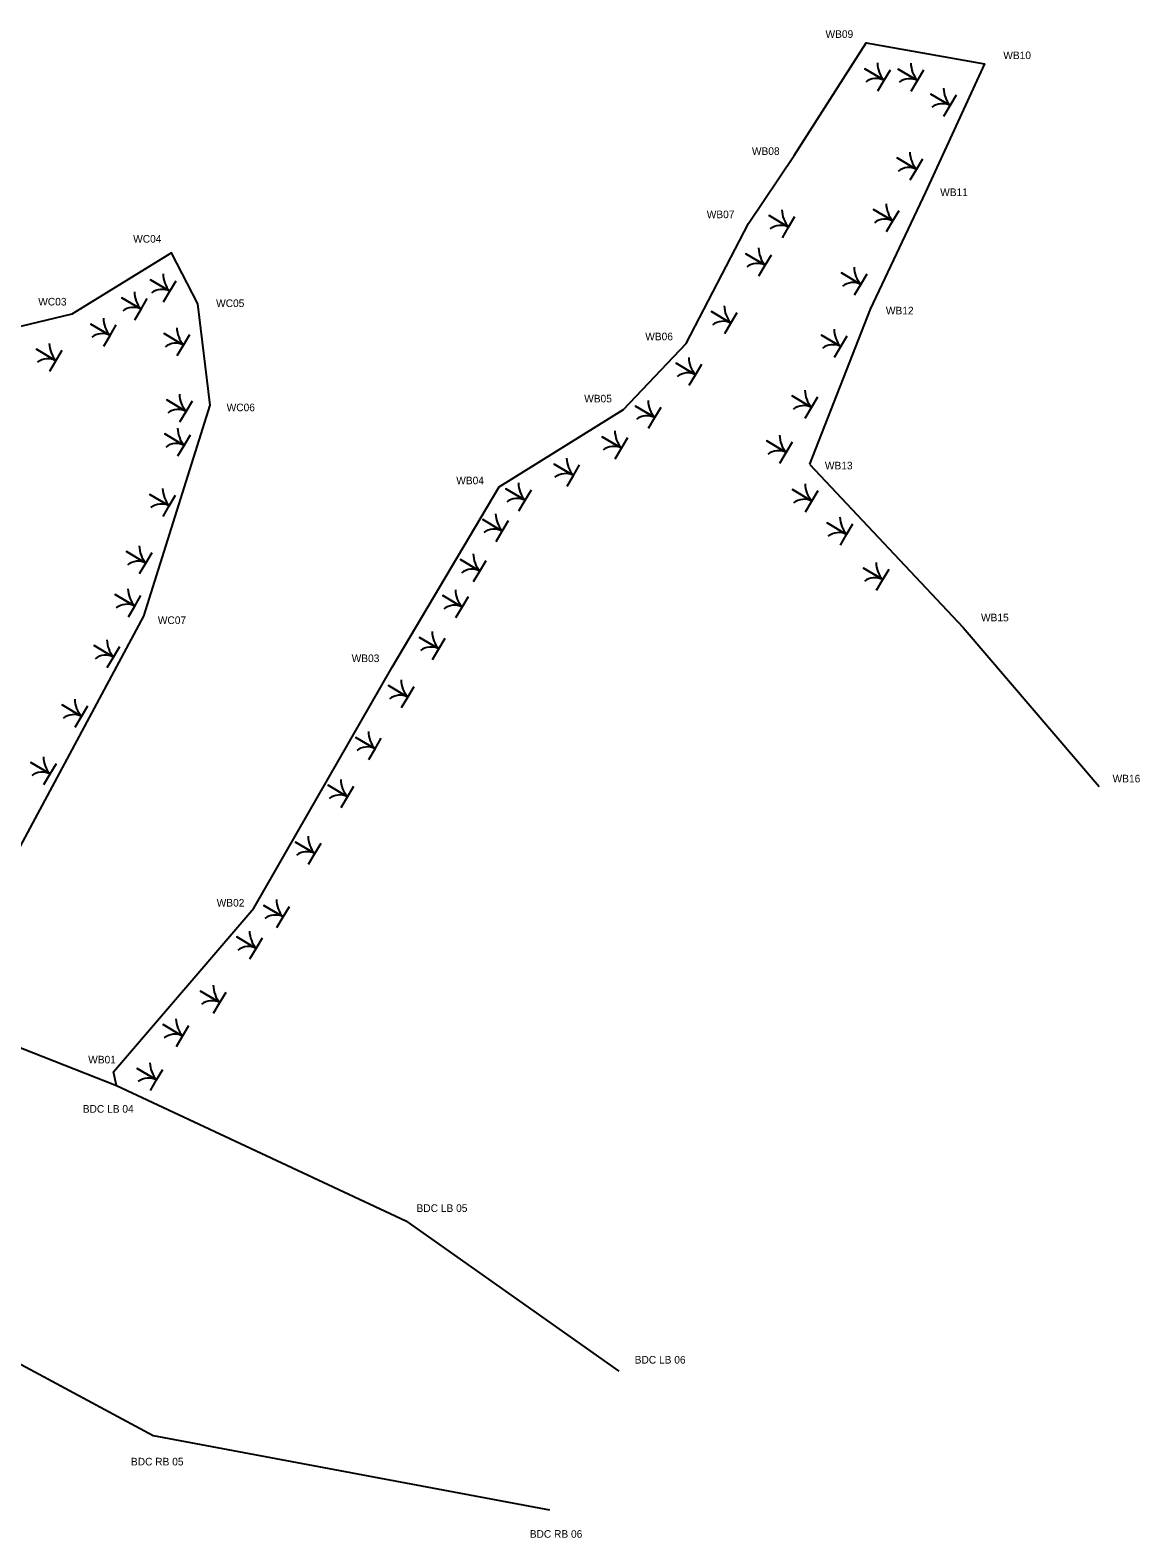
# Model space of a CAD drawing. Extents: x 2137594 to 2141353, y 404857 to 410633.
# Drawn here: x 2141060.9 to 2141352.6, y 410237.2 to 410633.5 of the extents above; entities that cross this region are included whole.
import ezdxf

# ---------------------------------------------------------------- set-up
doc = ezdxf.new("R2010")
doc.units = 0
for name, color, linetype in [('Exist Environmental Wetland Boundary', 7, 'Continuous'), ('Exist Environmental Wetland Boundary Text', 7, 'Continuous'), ('Exist Hydro Jurisdictional Stream or Body of Water', 7, 'Continuous')]:
    doc.layers.add(name, color=color, linetype=linetype)

msp = doc.modelspace()

# ---------------------------------------------------------------- linework, layer by layer
at = {"layer": 'Exist Environmental Wetland Boundary'}
for points in [[(2141083.61, 410356.07), (2141082.78, 410359.68), (2141119.71, 410402.68), (2141156.01, 410466), (2141184.14, 410513.4), (2141216.89, 410533.79), (2141233.31, 410551.13), (2141249.73, 410582.66), (2141261.7, 410600.5), (2141280.66, 410630.14), (2141311.76, 410624.67), (2141296.22, 410590.92), (2141281.69, 410560.1), (2141265.74, 410519.43)], [(2141283.72, 410617.53), (2141285.37, 410620.31), (2141280.28, 410623.33), (2141285.37, 410620.31), (2141287.01, 410623.08)], [(2141292.5, 410617.47), (2141294.14, 410620.24), (2141289.06, 410623.26), (2141294.14, 410620.24), (2141295.79, 410623.01)], [(2141301.09, 410610.89), (2141302.74, 410613.67), (2141297.65, 410616.69), (2141302.74, 410613.67), (2141304.39, 410616.44)], [(2141292.24, 410594.12), (2141293.88, 410596.89), (2141288.8, 410599.91), (2141293.88, 410596.89), (2141295.53, 410599.66)], [(2141286.02, 410580.54), (2141287.67, 410583.32), (2141282.58, 410586.34), (2141287.67, 410583.32), (2141289.31, 410586.09)], [(2141258.61, 410578.92), (2141260.26, 410581.7), (2141255.17, 410584.72), (2141260.26, 410581.7), (2141261.9, 410584.47)], [(2141050.59, 410369.05), (2141047.7, 410375.23), (2141041.81, 410383.44), (2141049.14, 410402), (2141090.77, 410479.46), (2141108.21, 410534.87), (2141105, 410561.51), (2141098.04, 410574.95), (2141071.82, 410558.85), (2141031.24, 410549.14), (2140984.72, 410568.16)], [(2141252.47, 410568.91), (2141254.12, 410571.69), (2141249.03, 410574.71), (2141254.12, 410571.69), (2141255.76, 410574.46)], [(2141095.94, 410562.08), (2141097.59, 410564.85), (2141092.5, 410567.87), (2141097.59, 410564.85), (2141099.24, 410567.63)], [(2141277.6, 410563.88), (2141279.24, 410566.65), (2141274.16, 410569.67), (2141279.24, 410566.65), (2141280.89, 410569.42)], [(2141088.39, 410557.36), (2141090.04, 410560.14), (2141084.95, 410563.16), (2141090.04, 410560.14), (2141091.68, 410562.91)], [(2141243.45, 410553.71), (2141245.09, 410556.48), (2141240, 410559.5), (2141245.09, 410556.48), (2141246.74, 410559.25)], [(2141080.24, 410550.45), (2141081.89, 410553.22), (2141076.8, 410556.24), (2141081.89, 410553.22), (2141083.53, 410555.99)], [(2141099.55, 410547.95), (2141101.2, 410550.72), (2141096.11, 410553.74), (2141101.2, 410550.72), (2141102.85, 410553.49)], [(2141272.32, 410547.55), (2141273.96, 410550.32), (2141268.87, 410553.34), (2141273.96, 410550.32), (2141275.61, 410553.09)], [(2141066.02, 410543.83), (2141067.67, 410546.6), (2141062.58, 410549.62), (2141067.67, 410546.6), (2141069.32, 410549.38)], [(2141234.13, 410540.14), (2141235.78, 410542.91), (2141230.69, 410545.93), (2141235.78, 410542.91), (2141237.42, 410545.68)], [(2141100.24, 410530.51), (2141101.89, 410533.28), (2141096.8, 410536.3), (2141101.89, 410533.28), (2141103.54, 410536.05)], [(2141264.65, 410531.53), (2141266.29, 410534.31), (2141261.21, 410537.33), (2141266.29, 410534.31), (2141267.94, 410537.08)], [(2141223.44, 410528.85), (2141225.09, 410531.63), (2141220, 410534.65), (2141225.09, 410531.63), (2141226.74, 410534.4)], [(2141099.74, 410521.57), (2141101.39, 410524.35), (2141096.3, 410527.37), (2141101.39, 410524.35), (2141103.03, 410527.12)], [(2141214.69, 410520.83), (2141216.34, 410523.6), (2141211.25, 410526.62), (2141216.34, 410523.6), (2141217.98, 410526.37)], [(2141257.99, 410519.69), (2141259.63, 410522.47), (2141254.55, 410525.49), (2141259.63, 410522.47), (2141261.28, 410525.24)], [(2141202.03, 410513.65), (2141203.68, 410516.42), (2141198.59, 410519.44), (2141203.68, 410516.42), (2141205.32, 410519.2)], [(2141265.74, 410519.43), (2141306.14, 410476.48), (2141341.86, 410434.69)], [(2141095.82, 410505.67), (2141097.47, 410508.44), (2141092.38, 410511.46), (2141097.47, 410508.44), (2141099.12, 410511.22)], [(2141189.34, 410507.14), (2141190.99, 410509.91), (2141185.9, 410512.93), (2141190.99, 410509.91), (2141192.64, 410512.68)], [(2141264.72, 410506.91), (2141266.37, 410509.69), (2141261.28, 410512.71), (2141266.37, 410509.69), (2141268.01, 410512.46)], [(2141183.35, 410499.06), (2141185, 410501.83), (2141179.91, 410504.85), (2141185, 410501.83), (2141186.64, 410504.61)], [(2141273.87, 410498.15), (2141275.51, 410500.92), (2141270.43, 410503.94), (2141275.51, 410500.92), (2141277.16, 410503.7)], [(2141089.65, 410490.62), (2141091.3, 410493.4), (2141086.21, 410496.42), (2141091.3, 410493.4), (2141092.95, 410496.17)], [(2141177.46, 410488.53), (2141179.1, 410491.3), (2141174.02, 410494.32), (2141179.1, 410491.3), (2141180.75, 410494.07)], [(2141283.36, 410486.27), (2141285, 410489.05), (2141279.92, 410492.07), (2141285, 410489.05), (2141286.65, 410491.82)], [(2141086.71, 410479.31), (2141088.36, 410482.09), (2141083.27, 410485.11), (2141088.36, 410482.09), (2141090, 410484.86)], [(2141172.8, 410479.06), (2141174.45, 410481.83), (2141169.36, 410484.85), (2141174.45, 410481.83), (2141176.09, 410484.61)], [(2141081.17, 410465.93), (2141082.82, 410468.71), (2141077.73, 410471.73), (2141082.82, 410468.71), (2141084.46, 410471.48)], [(2141166.64, 410468.08), (2141168.29, 410470.86), (2141163.2, 410473.88), (2141168.29, 410470.86), (2141169.94, 410473.63)], [(2141158.52, 410455.4), (2141160.16, 410458.17), (2141155.07, 410461.19), (2141160.16, 410458.17), (2141161.81, 410460.95)], [(2141072.74, 410450.31), (2141074.39, 410453.09), (2141069.3, 410456.11), (2141074.39, 410453.09), (2141076.03, 410455.86)], [(2141149.9, 410441.8), (2141151.55, 410444.57), (2141146.46, 410447.59), (2141151.55, 410444.57), (2141153.19, 410447.35)], [(2141064.48, 410435.19), (2141066.13, 410437.96), (2141061.04, 410440.98), (2141066.13, 410437.96), (2141067.77, 410440.73)], [(2141142.66, 410429.19), (2141144.3, 410431.96), (2141139.22, 410434.98), (2141144.3, 410431.96), (2141145.95, 410434.74)], [(2141134.05, 410414.27), (2141135.69, 410417.05), (2141130.6, 410420.07), (2141135.69, 410417.05), (2141137.34, 410419.82)], [(2141125.73, 410397.63), (2141127.37, 410400.4), (2141122.28, 410403.42), (2141127.37, 410400.4), (2141129.02, 410403.17)], [(2141118.65, 410389.35), (2141120.3, 410392.13), (2141115.21, 410395.15), (2141120.3, 410392.13), (2141121.95, 410394.9)], [(2141109.12, 410375.11), (2141110.76, 410377.88), (2141105.68, 410380.9), (2141110.76, 410377.88), (2141112.41, 410380.65)], [(2141099.32, 410366.29), (2141100.97, 410369.06), (2141095.88, 410372.08), (2141100.97, 410369.06), (2141102.62, 410371.84)], [(2141092.48, 410354.76), (2141094.13, 410357.53), (2141089.04, 410360.56), (2141094.13, 410357.53), (2141095.77, 410360.31)]]:
    msp.add_lwpolyline(points, dxfattribs=at)
for centre, radius, start, end in [((2141290.81, 410625.03), 7.21, 181.4367, 220.9314), ((2141299.59, 410624.96), 7.21, 181.4367, 220.9314), ((2141283.3, 410616.18), 4.61, 63.4496, 126.8442), ((2141292.08, 410616.11), 4.61, 63.4496, 126.8442), ((2141308.19, 410618.39), 7.21, 181.4367, 220.9314), ((2141300.68, 410609.54), 4.61, 63.4496, 126.8442), ((2141299.33, 410601.61), 7.21, 181.4367, 220.9314), ((2141291.82, 410592.76), 4.61, 63.4496, 126.8442), ((2141265.7, 410586.42), 7.21, 181.4367, 220.9314), ((2141293.11, 410588.04), 7.21, 181.4367, 220.9314), ((2141285.61, 410579.19), 4.61, 63.4496, 126.8442), ((2141258.2, 410577.57), 4.61, 63.4496, 126.8442), ((2141259.56, 410576.41), 7.21, 181.4367, 220.9314), ((2141252.06, 410567.56), 4.61, 63.4496, 126.8442), ((2141284.69, 410571.37), 7.21, 181.4367, 220.9314), ((2141103.03, 410569.58), 7.21, 181.4367, 220.9314), ((2141277.18, 410562.52), 4.61, 63.4496, 126.8442), ((2141095.48, 410564.86), 7.21, 181.4367, 220.9314), ((2141095.53, 410560.73), 4.61, 63.4496, 126.8442), ((2141087.97, 410556.01), 4.61, 63.4496, 126.8442), ((2141250.54, 410561.2), 7.21, 181.4367, 220.9314), ((2141087.33, 410557.94), 7.21, 181.4367, 220.9314), ((2141106.65, 410555.44), 7.21, 181.4367, 220.9314), ((2141243.03, 410552.35), 4.61, 63.4496, 126.8442), ((2141279.41, 410555.04), 7.21, 181.4367, 220.9314), ((2141073.12, 410551.33), 7.21, 181.4367, 220.9314), ((2141079.83, 410549.1), 4.61, 63.4496, 126.8442), ((2141099.14, 410546.59), 4.61, 63.4496, 126.8442), ((2141271.9, 410546.2), 4.61, 63.4496, 126.8442), ((2141065.61, 410542.48), 4.61, 63.4496, 126.8442), ((2141241.22, 410547.63), 7.21, 181.4367, 220.9314), ((2141233.72, 410538.78), 4.61, 63.4496, 126.8442), ((2141271.74, 410539.03), 7.21, 181.4367, 220.9314), ((2141107.34, 410538), 7.21, 181.4367, 220.9314), ((2141230.54, 410536.35), 7.21, 181.4367, 220.9314), ((2141264.23, 410530.18), 4.61, 63.4496, 126.8442), ((2141099.83, 410529.16), 4.61, 63.4496, 126.8442), ((2141223.03, 410527.5), 4.61, 63.4496, 126.8442), ((2141106.83, 410529.07), 7.21, 181.4367, 220.9314), ((2141221.78, 410528.32), 7.21, 181.4367, 220.9314), ((2141265.08, 410527.19), 7.21, 181.4367, 220.9314), ((2141099.33, 410520.22), 4.61, 63.4496, 126.8442), ((2141214.27, 410519.47), 4.61, 63.4496, 126.8442), ((2141257.57, 410518.34), 4.61, 63.4496, 126.8442), ((2141209.12, 410521.15), 7.21, 181.4367, 220.9314), ((2141201.61, 410512.3), 4.61, 63.4496, 126.8442), ((2141102.91, 410513.17), 7.21, 181.4367, 220.9314), ((2141196.43, 410514.63), 7.21, 181.4367, 220.9314), ((2141271.81, 410514.41), 7.21, 181.4367, 220.9314), ((2141095.41, 410504.32), 4.61, 63.4496, 126.8442), ((2141188.93, 410505.78), 4.61, 63.4496, 126.8442), ((2141264.31, 410505.56), 4.61, 63.4496, 126.8442), ((2141190.44, 410506.56), 7.21, 181.4367, 220.9314), ((2141280.96, 410505.65), 7.21, 181.4367, 220.9314), ((2141182.93, 410497.71), 4.61, 63.4496, 126.8442), ((2141273.45, 410496.8), 4.61, 63.4496, 126.8442), ((2141096.75, 410498.12), 7.21, 181.4367, 220.9314), ((2141184.55, 410496.02), 7.21, 181.4367, 220.9314), ((2141089.24, 410489.27), 4.61, 63.4496, 126.8442), ((2141177.04, 410487.18), 4.61, 63.4496, 126.8442), ((2141290.45, 410493.77), 7.21, 181.4367, 220.9314), ((2141282.94, 410484.92), 4.61, 63.4496, 126.8442), ((2141093.8, 410486.81), 7.21, 181.4367, 220.9314), ((2141179.89, 410486.56), 7.21, 181.4367, 220.9314), ((2141086.3, 410477.96), 4.61, 63.4496, 126.8442), ((2141172.38, 410477.71), 4.61, 63.4496, 126.8442), ((2141173.74, 410475.58), 7.21, 181.4367, 220.9314), ((2141088.26, 410473.43), 7.21, 181.4367, 220.9314), ((2141166.23, 410466.73), 4.61, 63.4496, 126.8442), ((2141080.76, 410464.58), 4.61, 63.4496, 126.8442), ((2141165.61, 410462.9), 7.21, 181.4367, 220.9314), ((2141079.83, 410457.81), 7.21, 181.4367, 220.9314), ((2141158.1, 410454.05), 4.61, 63.4496, 126.8442), ((2141072.32, 410448.96), 4.61, 63.4496, 126.8442), ((2141156.99, 410449.29), 7.21, 181.4367, 220.9314), ((2141149.49, 410440.45), 4.61, 63.4496, 126.8442), ((2141071.57, 410442.68), 7.21, 181.4367, 220.9314), ((2141064.07, 410433.84), 4.61, 63.4496, 126.8442), ((2141149.75, 410436.69), 7.21, 181.4367, 220.9314), ((2141142.24, 410427.84), 4.61, 63.4496, 126.8442), ((2141141.14, 410421.77), 7.21, 181.4367, 220.9314), ((2141133.63, 410412.92), 4.61, 63.4496, 126.8442), ((2141132.82, 410405.12), 7.21, 181.4367, 220.9314), ((2141125.31, 410396.28), 4.61, 63.4496, 126.8442), ((2141125.75, 410396.85), 7.21, 181.4367, 220.9314), ((2141118.24, 410388), 4.61, 63.4496, 126.8442), ((2141116.21, 410382.6), 7.21, 181.4367, 220.9314), ((2141108.7, 410373.75), 4.61, 63.4496, 126.8442), ((2141106.42, 410373.79), 7.21, 181.4367, 220.9314), ((2141098.91, 410364.94), 4.61, 63.4496, 126.8442), ((2141099.57, 410362.26), 7.21, 181.4367, 220.9314), ((2141092.07, 410353.41), 4.61, 63.4496, 126.8442)]:
    msp.add_arc(centre, radius, start, end, dxfattribs=at)
at = {"layer": 'Exist Hydro Jurisdictional Stream or Body of Water'}
for points in [[(2140883.62, 410376.03), (2140976.51, 410357.37), (2141050.59, 410369.05), (2141083.61, 410356.07), (2141159.67, 410320.47), (2141215.66, 410280.98)], [(2140871.91, 410353.89), (2140953.94, 410339.14), (2141013.64, 410310.26), (2141042.28, 410291.41), (2141093.26, 410264.05), (2141197.43, 410244.52)]]:
    msp.add_lwpolyline(points, dxfattribs=at)

# ---------------------------------------------------------------- texts
at = {"layer": 'Exist Environmental Wetland Boundary Text'}
for s, p in [('WB09', (2141269.96, 410631.45)), ('WB10', (2141316.69, 410625.87)), ('WB08', (2141250.61, 410600.69)), ('WB11', (2141300.1, 410589.88)), ('WB07', (2141238.74, 410584.05)), ('WC04', (2141087.96, 410577.63)), ('WC03', (2141063.01, 410561.11)), ('WC05', (2141109.76, 410560.7)), ('WB12', (2141285.83, 410558.77)), ('WB06', (2141222.57, 410551.96)), ('WC06', (2141112.54, 410533.31)), ('WB05', (2141206.52, 410535.63)), ('WB13', (2141269.8, 410518.03)), ('WB04', (2141172.89, 410514.11)), ('WC07', (2141094.45, 410477.39)), ('WB15', (2141310.83, 410478.09)), ('WB03', (2141145.4, 410467.38)), ('WB16', (2141345.42, 410435.75)), ('WB02', (2141109.92, 410403.1)), ('WB01', (2141076.14, 410361.88)), ('BDC LB 04', (2141074.72, 410348.93)), ('BDC LB 05', (2141162.45, 410322.84)), ('BDC LB 06', (2141219.8, 410282.98)), ('BDC RB 05', (2141087.38, 410256.21)), ('BDC RB 06', (2141192.21, 410237.2))]:
    msp.add_text(s, height=2, dxfattribs=at).set_placement(p)

doc.saveas('drawing.dxf')
